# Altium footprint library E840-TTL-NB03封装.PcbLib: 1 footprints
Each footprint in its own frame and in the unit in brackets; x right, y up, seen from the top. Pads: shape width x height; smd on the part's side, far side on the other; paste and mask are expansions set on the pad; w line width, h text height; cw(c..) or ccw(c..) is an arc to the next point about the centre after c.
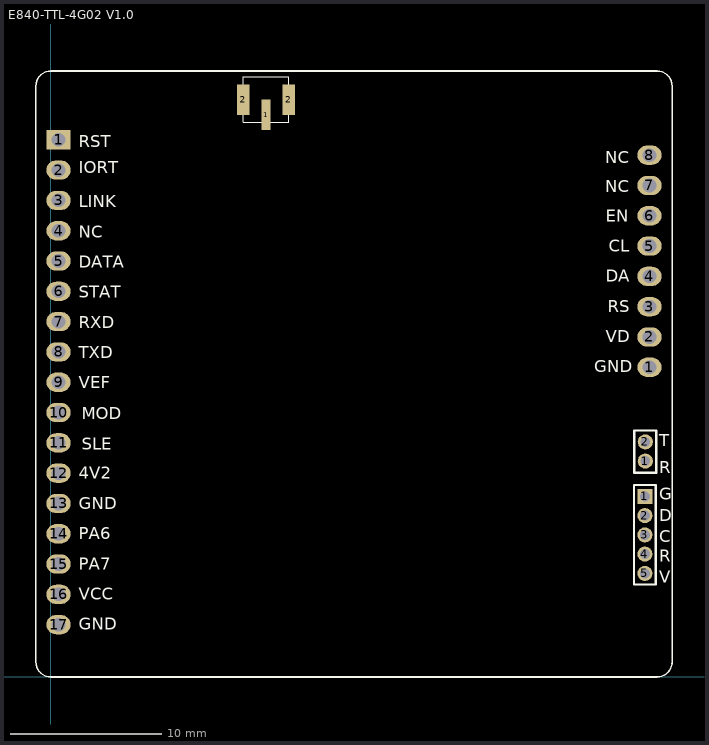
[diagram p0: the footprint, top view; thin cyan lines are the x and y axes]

## E840-TTL-4G02 V1.0 [mm]
pads (35):
  rect 1.6x1.27 hole 0.9: 1(0.5,35.455)
  rect 0.6x2 smd: 1(14.193,37.107)
  rect 1x1 hole 0.65 mask+0.05: 1(39.196,11.92)
  round 1 hole 0.65 mask+0.05: 1(39.226,14.247) 2(39.196,10.65) 2(39.226,15.52) 3(39.196,9.38) 4(39.196,8.11) 5(39.196,6.84)
  oval 1.6x1.27 hole 0.9: 1(39.5,20.442) 2(0.5,33.455) 2(39.5,22.442) 3(0.5,31.455) 3(39.5,24.442) 4(0.5,29.455) 4(39.5,26.442) 5(0.5,27.455) 5(39.5,28.442) 6(0.5,25.455) 6(39.5,30.442) 7(0.5,23.455) 7(39.5,32.442) 8(0.5,21.455) 8(39.5,34.442) 9(0.5,19.455) 10(0.5,17.455) 11(0.5,15.455) 12(0.5,13.455) 13(0.5,11.455) 14(0.5,9.455) 15(0.5,7.455) 16(0.5,5.455) 17(0.5,3.455)
  rect 0.8x2 smd: 2(12.693,38.107) 2(15.693,38.107)
Mid-Layer 2:
  lines w0.254: 0.351,20.991 0.928,20.991
Top Overlay:
  lines w0.076: 12.693,36.607 15.693,36.607 15.693,39.607 12.693,39.607 12.693,36.607
  lines w0.1: -1,1 ccw(c0,1) 0,0 40,0 ccw(c40,1) 41,1 41,39 ccw(c40.002,38.998) 40,39.996 0,39.996 ccw(c-0.002,38.998) -1,39 -1,1
  lines w0.15: 38.483,6.107 38.483,12.678 39.918,12.678 39.918,6.107 38.483,6.107 ; 38.504,13.489 39.94,13.489 39.94,16.273 38.504,16.273 38.504,13.489
  text "RST" at 1.838,34.972 h0.8
  text "IORT" at 1.838,33.247 h0.8
  text "LINK" at 1.838,30.989 h0.8
  text "NC" at 1.838,28.998 h0.8
  text "DATA" at 1.838,27.007 h0.8
  text "STAT" at 1.838,25.016 h0.8
  text "RXD" at 1.838,23.024 h0.8
  text "TXD" at 1.838,21.033 h0.8
  text "VEF" at 1.838,19.042 h0.8
  text "MOD" at 2.032,17.018 h0.8
  text "SLE" at 2.032,14.986 h0.8
  text "4V2" at 1.838,13.068 h0.8
  text "GND" at 1.838,11.077 h0.8
  text "PA6" at 1.838,9.086 h0.8
  text "PA7" at 1.838,7.094 h0.8
  text "VCC" at 1.838,5.103 h0.8
  text "GND" at 1.838,3.112 h0.8
  text "NC" at 36.576,33.909 h0.8
  text "NC" at 36.576,32.004 h0.8
  text "EN" at 36.622,30.046 h0.8
  text "CL" at 36.808,28.058 h0.8
  text "DA" at 36.625,26.071 h0.8
  text "RS" at 36.743,24.083 h0.8
  text "VD" at 36.629,22.096 h0.8
  text "GND" at 35.87,20.108 h0.8
  text "V" at 40.132,6.223 h0.8
  text "R" at 40.132,7.62 h0.8
  text "C" at 40.132,8.89 h0.8
  text "D" at 40.132,10.287 h0.8
  text "G" at 40.132,11.684 h0.8
  text "R" at 40.132,13.462 h0.8
  text "T" at 40.132,15.24 h0.8
Bottom Overlay:
  lines w0.1: 27.355,17.327 22.895,17.327 22.895,0.127 38.195,0.127 38.195,15.767 38.195,15.937 27.365,15.937 ; 27.359,15.937 27.372,17.327
  lines w0.203: -0.719,34.439 1.719,34.439 ; 38.281,21.458 40.719,21.458 ; 40.694,35.712 38.281,35.712 38.281,19.198 40.719,19.198 40.719,35.712 ; -0.719,2.295 1.719,2.295 1.719,36.7 -0.719,36.7 -0.719,2.295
